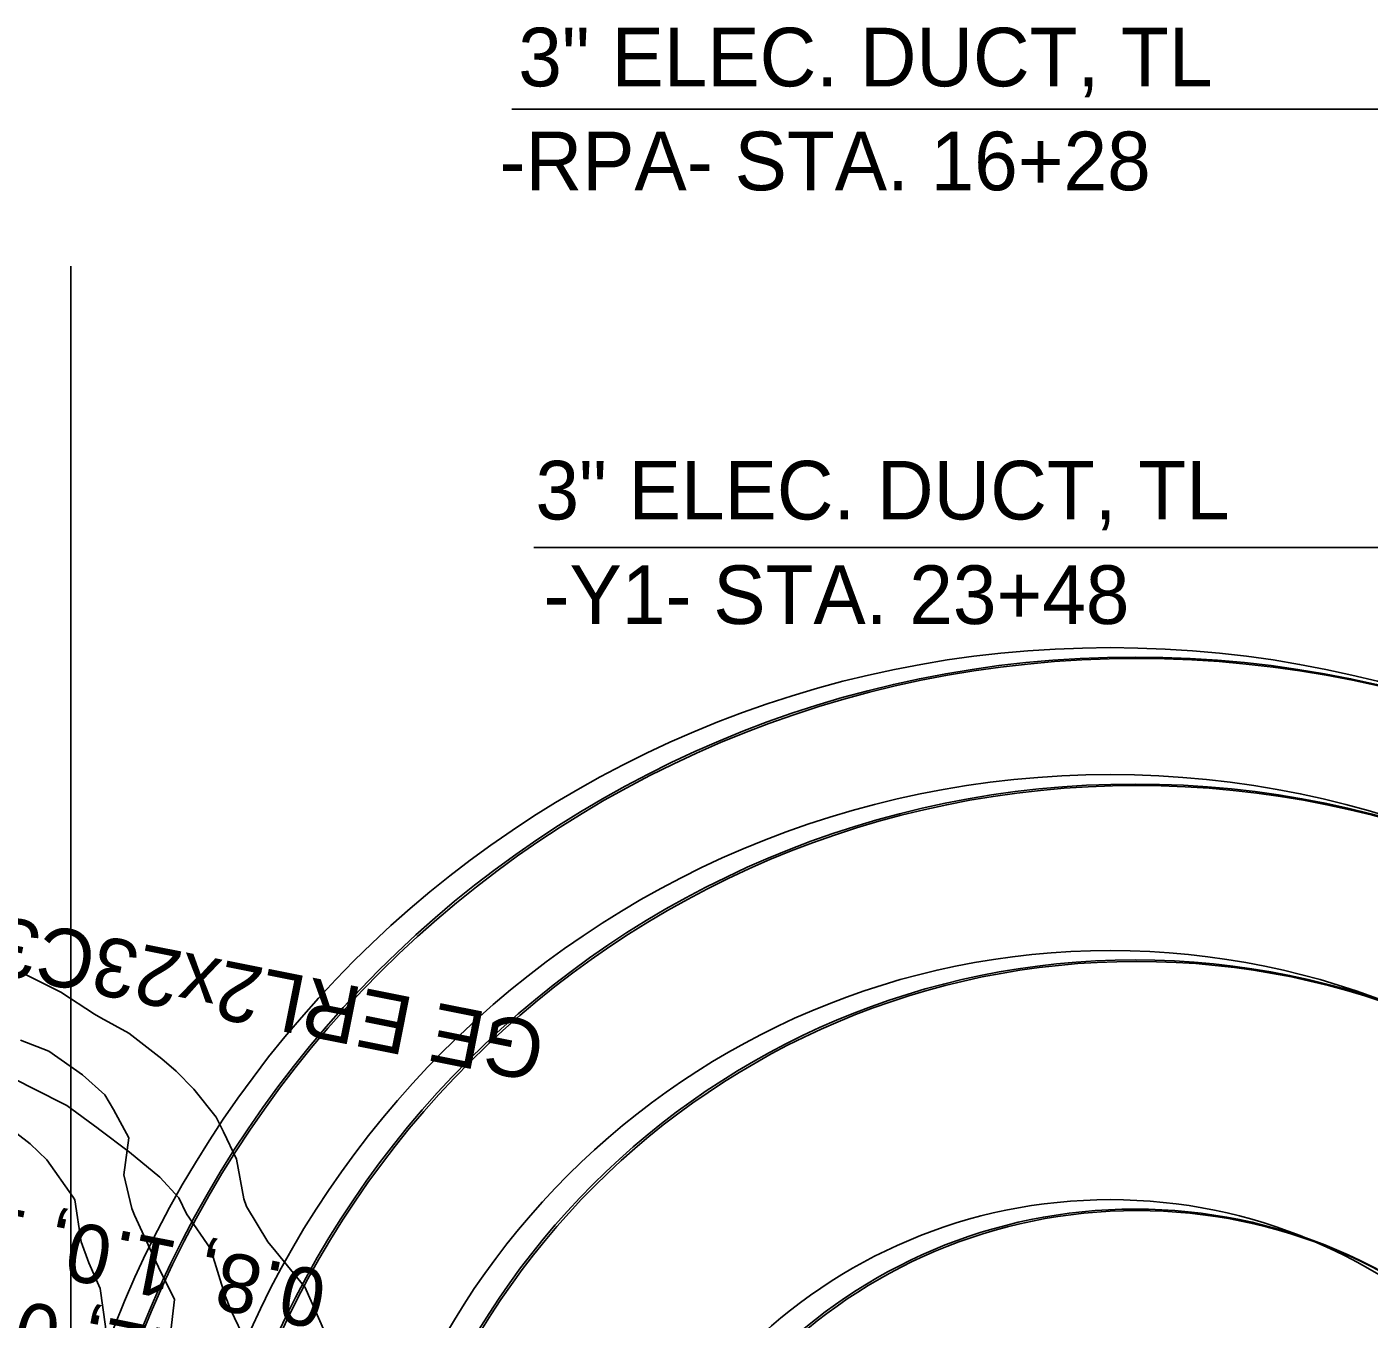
# Model space of a CAD drawing. Extents: x 1638506 to 1658005, y 834807 to 846788.
# Drawn here: x 1640408.1 to 1640682.9, y 842698.3 to 842962.9 of the extents above; entities that cross this region are included whole.
import ezdxf

# ---------------------------------------------------------------- set-up
doc = ezdxf.new("R2010")
doc.units = 0
for name, color, linetype in [('Default', 7, 'Continuous'), ('Old_Level_1', 7, 'Continuous'), ('Old_Level_2', 7, 'Continuous'), ('Old_Level_4', 7, 'Continuous'), ('Scratch_Level_0', 7, 'Continuous')]:
    doc.layers.add(name, color=color, linetype=linetype)

msp = doc.modelspace()

# ---------------------------------------------------------------- linework, layer by layer
at = {"layer": 'Default'}
for p, q in [((1640507.38, 842946.07), (1640714.43, 842946.07)), ((1640417.09, 842265.25), (1640417.09, 842913.91)), ((1640511.86, 842856.33), (1640721.43, 842856.33))]:
    msp.add_line(p, q, dxfattribs=at)
at = {"layer": 'Old_Level_1'}
for points in [[(1640452.87, 842693.78), (1640449.83, 842700.18), (1640448.53, 842703.5), (1640445.96, 842711.9), (1640445.7, 842712.67), (1640440.73, 842719.9), (1640439.15, 842723.2), (1640435.31, 842727.39), (1640429.05, 842732.55), (1640422.71, 842737.32), (1640422.66, 842737.36), (1640416.23, 842742.07), (1640409.37, 842745.59), (1640402.5, 842749.07)], [(1640404.66, 842665.52), (1640411.74, 842668.04), (1640414.41, 842669.97), (1640418.93, 842673.57), (1640422, 842680.59), (1640423.26, 842688.27), (1640424.27, 842696.05), (1640424.19, 842696.83), (1640423.11, 842704.61), (1640420.79, 842709.85), (1640419.19, 842714.18), (1640417.86, 842722.8), (1640417.54, 842723.3), (1640412.19, 842730.97), (1640408.78, 842734.25), (1640406.01, 842736.34)]]:
    msp.add_lwpolyline(points, dxfattribs=at)
for radius in [219, 193, 157, 106]:
    msp.add_circle((1640635.3, 842614.58), radius, dxfattribs=at)
at = {"layer": 'Old_Level_2'}
msp.add_arc((1640787.74, 844492.39), 1882, 251.76578, 273.94492, dxfattribs=at)
at = {"layer": 'Old_Level_4'}
for radius in [219, 193, 157, 106]:
    msp.add_circle((1640629.86, 842616.81), radius, dxfattribs=at)
at = {"layer": 'Scratch_Level_0'}
for points in [[(1640468.8, 842696.32), (1640465.27, 842704.38), (1640465.07, 842704.86), (1640459.02, 842712.17), (1640457.39, 842714.19), (1640453.06, 842721.38), (1640452.47, 842722.97), (1640450.98, 842731.07), (1640448.3, 842736.67), (1640446.82, 842739.7), (1640442.25, 842745.45), (1640438.66, 842749.13), (1640435.69, 842751.67), (1640428.94, 842756.92), (1640423.2, 842760.01), (1640421.91, 842760.8), (1640415.01, 842765.3), (1640407.92, 842768.85)], [(1640403.87, 842670.27), (1640412.45, 842674.19), (1640415.07, 842675.82), (1640421.5, 842680.48), (1640423.37, 842681.97), (1640430.84, 842688.2), (1640430.92, 842688.27), (1640437.39, 842694.78), (1640438.29, 842702.4), (1640434.99, 842709.01), (1640434.06, 842711.04), (1640430.09, 842719.63), (1640429.58, 842721.02), (1640427.89, 842727.87), (1640428.92, 842735.47), (1640425.82, 842741.29), (1640424.04, 842744.24), (1640419.43, 842748.36), (1640412.6, 842753.2), (1640406.74, 842755.49)]]:
    msp.add_lwpolyline(points, dxfattribs=at)
for radius in [219, 193, 157, 106]:
    msp.add_circle((1640634.95, 842614.89), radius, dxfattribs=at)

# ---------------------------------------------------------------- texts
at = {"layer": 'Default'}
for s, p in [('3" ELEC. DUCT, TL', (1640508.68, 842950.71)), ('-RPA- STA. 16+28', (1640504.82, 842929.44)), ('3" ELEC. DUCT, TL', (1640512.2, 842862.05)), ('-Y1- STA. 23+48', (1640513.82, 842840.65))]:
    msp.add_text(s, height=12, dxfattribs=at).set_placement(p)
at = {"layer": 'Scratch_Level_0'}
for s, p in [('GE ERL2x23C340', (1640514.8, 842758.65)), ('0.8, 1.0, 1.2', (1640470.05, 842708)), ('0.1, 0.2, 0.4,', (1640476.9, 842688.28))]:
    msp.add_text(s, height=12, rotation=168.7284, dxfattribs=at).set_placement(p)

doc.saveas('drawing.dxf')
